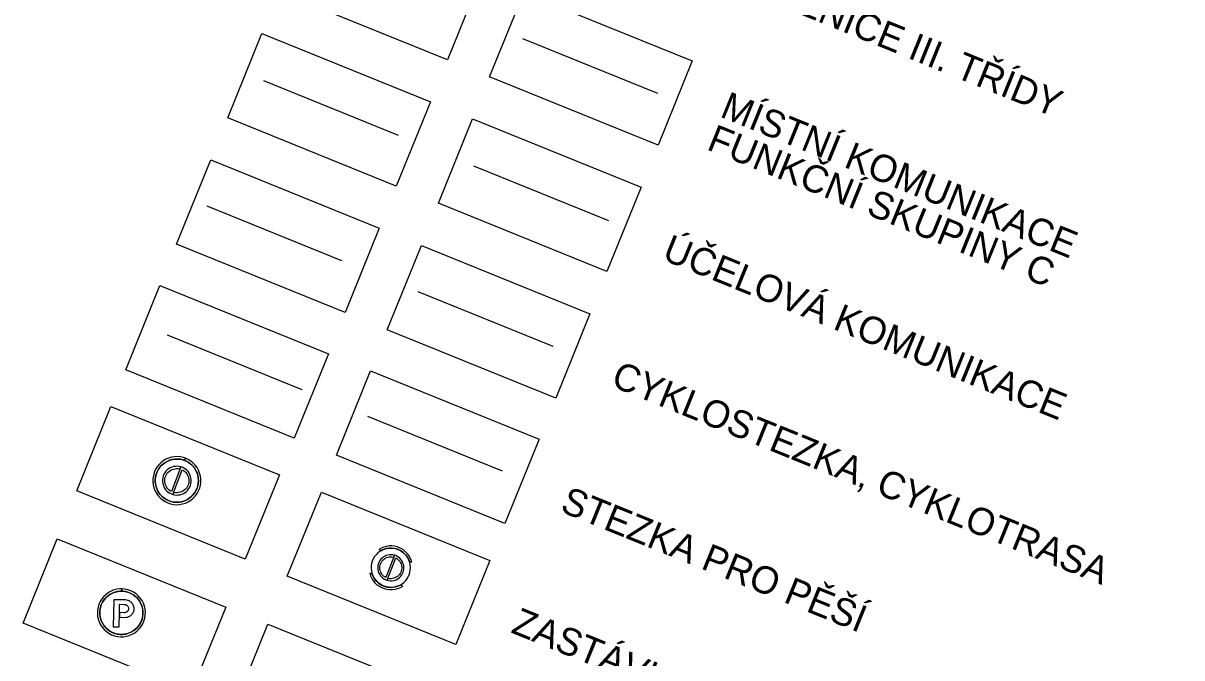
# Model space of a CAD drawing. Extents: x -522763 to -519637, y -1191176 to -1188936.
# Drawn here: x -522606 to -521969, y -1189589 to -1189240 of the extents above; entities that cross this region are included whole.
import ezdxf

# ---------------------------------------------------------------- set-up
doc = ezdxf.new("R2010")
doc.units = 0
for name, color, linetype in [('cyklostezka_s', 7, 'Continuous'), ('Implicitní', 7, 'Continuous'), ('ložisk_nerost', 7, 'Continuous'), ('MK_C_n', 7, 'Continuous'), ('stezka_s', 7, 'Continuous'), ('zast_HD_n', 7, 'Continuous'), ('zast_HD_s', 7, 'Continuous')]:
    doc.layers.add(name, color=color, linetype=linetype)

msp = doc.modelspace()

# ---------------------------------------------------------------- linework, layer by layer
at = {"layer": 'cyklostezka_s'}
msp.add_line((-522505.25, -1189340.46), (-522431.11, -1189370.51), dxfattribs=at)
at = {"layer": 'Implicitní'}
for p, q in [((-522474.07, -1189271.68), (-522399.92, -1189301.73)), ((-522358.48, -1189318.53), (-522284.34, -1189348.58)), ((-522389.06, -1189387.55), (-522314.92, -1189417.6)), ((-522416.84, -1189456.08), (-522342.7, -1189486.13))]:
    msp.add_line(p, q, dxfattribs=at)
for points in [[(-522446.72, -1189176.27), (-522354.04, -1189213.83), (-522372.82, -1189260.17), (-522465.5, -1189222.61)], [(-522330.87, -1189223.22), (-522238.19, -1189260.78), (-522256.97, -1189307.12), (-522349.65, -1189269.56)], [(-522474.89, -1189245.78), (-522382.21, -1189283.34), (-522400.99, -1189329.68), (-522493.67, -1189292.12)], [(-522359.04, -1189292.73), (-522266.36, -1189330.29), (-522285.14, -1189376.63), (-522377.82, -1189339.07)], [(-522503.06, -1189315.29), (-522410.38, -1189352.85), (-522429.16, -1189399.19), (-522521.84, -1189361.63)], [(-522387.21, -1189362.24), (-522294.53, -1189399.8), (-522313.31, -1189446.14), (-522405.99, -1189408.58)], [(-522531, -1189384.24), (-522438.33, -1189421.8), (-522457.11, -1189468.14), (-522549.78, -1189430.58)], [(-522415.16, -1189431.19), (-522322.48, -1189468.75), (-522341.26, -1189515.09), (-522433.94, -1189477.53)], [(-522558, -1189450.84), (-522465.32, -1189488.4), (-522484.1, -1189534.74), (-522576.78, -1189497.18)], [(-522442.15, -1189497.79), (-522349.47, -1189535.35), (-522368.25, -1189581.69), (-522460.93, -1189544.13)], [(-522587.44, -1189523.5), (-522494.77, -1189561.06), (-522513.55, -1189607.4), (-522606.22, -1189569.84)], [(-522471.6, -1189570.45), (-522378.92, -1189608.01), (-522397.7, -1189654.35), (-522490.38, -1189616.79)]]:
    msp.add_lwpolyline(points, close=True, dxfattribs=at)
at = {"layer": 'ložisk_nerost'}
for points in [[(-522551.92, -1189550.99), (-522553.02, -1189551.02), (-522554.68, -1189551.23), (-522556.29, -1189551.64), (-522557.85, -1189552.26), (-522559.31, -1189553.07), (-522560.66, -1189554.05), (-522561.87, -1189555.2), (-522562.93, -1189556.49), (-522563.81, -1189557.91), (-522564.52, -1189559.42), (-522565.02, -1189561.01), (-522565.32, -1189562.66), (-522565.41, -1189564.32), (-522565.29, -1189565.99), (-522564.96, -1189567.63), (-522564.42, -1189569.21), (-522563.69, -1189570.71), (-522562.78, -1189572.11), (-522561.7, -1189573.38), (-522560.46, -1189574.51), (-522559.1, -1189575.47), (-522557.62, -1189576.25), (-522556.06, -1189576.83), (-522554.43, -1189577.22), (-522552.77, -1189577.4), (-522551.1, -1189577.36), (-522549.45, -1189577.12), (-522547.84, -1189576.67), (-522546.3, -1189576.02), (-522544.86, -1189575.18), (-522543.53, -1189574.17), (-522542.35, -1189572.99), (-522541.31, -1189571.68), (-522540.46, -1189570.25), (-522539.79, -1189568.72), (-522539.32, -1189567.11), (-522539.05, -1189565.47), (-522539, -1189563.8), (-522539.15, -1189562.13), (-522539.52, -1189560.5), (-522540.09, -1189558.93), (-522540.85, -1189557.45), (-522541.79, -1189556.07), (-522542.9, -1189554.82), (-522544.16, -1189553.72), (-522545.55, -1189552.79), (-522547.04, -1189552.04), (-522548.61, -1189551.49), (-522550.25, -1189551.14), (-522551.91, -1189551)], [(-522540.32, -1189564.46), (-522540.38, -1189562.96), (-522540.63, -1189561.47), (-522541.07, -1189560.04), (-522541.68, -1189558.66), (-522542.46, -1189557.38), (-522543.4, -1189556.21), (-522544.48, -1189555.16), (-522545.68, -1189554.26), (-522546.99, -1189553.52), (-522548.38, -1189552.94), (-522549.83, -1189552.55), (-522551.32, -1189552.34), (-522552.82, -1189552.33), (-522554.31, -1189552.5), (-522555.77, -1189552.86), (-522557.18, -1189553.4), (-522558.5, -1189554.12), (-522559.72, -1189554.99), (-522560.82, -1189556.01), (-522561.79, -1189557.17), (-522562.6, -1189558.43), (-522563.24, -1189559.79), (-522563.71, -1189561.22), (-522563.99, -1189562.7), (-522564.09, -1189564.2), (-522564, -1189565.7), (-522563.71, -1189567.17), (-522563.25, -1189568.6), (-522562.6, -1189569.96), (-522561.79, -1189571.22), (-522560.83, -1189572.38), (-522559.73, -1189573.4), (-522558.51, -1189574.28), (-522557.19, -1189574.99), (-522555.78, -1189575.54), (-522554.33, -1189575.9), (-522552.83, -1189576.07), (-522551.33, -1189576.06), (-522549.84, -1189575.85), (-522548.39, -1189575.46), (-522547, -1189574.89), (-522545.69, -1189574.15), (-522544.49, -1189573.25), (-522543.41, -1189572.2), (-522542.47, -1189571.03), (-522541.69, -1189569.75), (-522541.07, -1189568.38), (-522540.63, -1189566.94), (-522540.38, -1189565.46), (-522540.32, -1189564.46)], [(-522551.94, -1189552.31), (-522550.95, -1189552.38), (-522549.47, -1189552.63), (-522548.03, -1189553.07), (-522546.66, -1189553.68), (-522545.38, -1189554.46), (-522544.2, -1189555.4), (-522543.16, -1189556.48), (-522542.26, -1189557.69), (-522541.51, -1189558.99), (-522540.94, -1189560.38), (-522540.55, -1189561.83), (-522540.34, -1189563.32), (-522540.33, -1189564.83), (-522540.5, -1189566.32), (-522540.86, -1189567.78), (-522541.41, -1189569.18), (-522542.12, -1189570.5), (-522543, -1189571.72), (-522544.02, -1189572.83), (-522545.17, -1189573.79), (-522546.44, -1189574.6), (-522547.8, -1189575.24), (-522549.22, -1189575.71), (-522550.7, -1189575.99), (-522552.2, -1189576.09), (-522553.7, -1189575.99), (-522555.18, -1189575.71), (-522556.61, -1189575.24), (-522557.96, -1189574.6), (-522559.23, -1189573.79), (-522560.38, -1189572.83), (-522561.41, -1189571.72), (-522562.28, -1189570.5), (-522563, -1189569.18), (-522563.54, -1189567.78), (-522563.9, -1189566.32), (-522564.07, -1189564.83), (-522564.06, -1189563.32), (-522563.85, -1189561.83), (-522563.46, -1189560.38), (-522562.89, -1189558.99), (-522562.15, -1189557.69), (-522561.25, -1189556.48), (-522560.2, -1189555.4), (-522559.03, -1189554.47), (-522557.74, -1189553.68), (-522556.37, -1189553.07), (-522554.93, -1189552.63), (-522553.45, -1189552.38), (-522551.95, -1189552.31)], [(-522551.95, -1189552.31), (-522551.92, -1189550.99)], [(-522551.91, -1189551), (-522551.94, -1189552.31)], [(-522549.88, -1189557.12), (-522556.33, -1189556.98), (-522556.65, -1189571.87), (-522553.48, -1189571.94), (-522553.31, -1189564.09)], [(-522550.09, -1189566.74), (-522549.38, -1189566.63), (-522548.91, -1189566.53), (-522548.56, -1189566.42), (-522548.2, -1189566.31), (-522547.96, -1189566.2), (-522547.73, -1189566.08), (-522547.37, -1189565.86), (-522547.01, -1189565.63), (-522546.77, -1189565.4), (-522546.53, -1189565.17), (-522546.29, -1189564.94), (-522546.05, -1189564.6), (-522545.81, -1189564.25), (-522545.69, -1189564.02), (-522545.57, -1189563.79), (-522545.44, -1189563.44), (-522545.32, -1189563.09), (-522545.19, -1189562.5), (-522545.18, -1189562.15), (-522545.17, -1189561.68), (-522545.27, -1189561.1), (-522545.27, -1189560.98), (-522545.38, -1189560.62), (-522545.49, -1189560.27), (-522545.72, -1189559.79), (-522545.94, -1189559.44), (-522546.17, -1189559.08), (-522546.4, -1189558.84), (-522546.63, -1189558.6), (-522546.86, -1189558.36), (-522547.2, -1189558.12), (-522547.55, -1189557.88), (-522547.78, -1189557.76), (-522548.01, -1189557.63), (-522548.36, -1189557.51), (-522548.59, -1189557.39), (-522549.18, -1189557.26), (-522549.88, -1189557.12)], [(-522553.26, -1189564.09), (-522553.32, -1189566.67)], [(-522553.31, -1189564.09), (-522553.21, -1189559.51)], [(-522550.73, -1189564.14), (-522553.26, -1189564.09)], [(-522553.21, -1189559.51), (-522550.64, -1189559.57)], [(-522550.64, -1189559.57), (-522550.52, -1189559.57), (-522550.4, -1189559.58), (-522549.82, -1189559.71), (-522549.59, -1189559.83), (-522549.35, -1189559.95), (-522549.12, -1189560.07), (-522548.89, -1189560.31), (-522548.66, -1189560.55), (-522548.44, -1189560.91), (-522548.33, -1189561.26), (-522548.22, -1189561.85), (-522548.23, -1189562.08), (-522548.35, -1189562.55), (-522548.48, -1189562.9), (-522548.72, -1189563.25), (-522548.84, -1189563.36), (-522549.08, -1189563.59), (-522549.44, -1189563.82), (-522549.67, -1189563.93), (-522550.03, -1189564.04), (-522550.5, -1189564.15), (-522550.73, -1189564.14)], [(-522553.32, -1189566.67), (-522550.09, -1189566.74)]]:
    msp.add_lwpolyline(points, dxfattribs=at)
at = {"layer": 'MK_C_n'}
msp.add_line((-522331.55, -1189248.52), (-522257.41, -1189278.57), dxfattribs=at)
at = {"layer": 'stezka_s'}
msp.add_line((-522527.05, -1189411.42), (-522452.9, -1189441.47), dxfattribs=at)
at = {"layer": 'zast_HD_n'}
msp.add_line((-522406.01, -1189546.33), (-522406.01, -1189546.33), dxfattribs=at)
for points in [[(-522393.93, -1189543.3), (-522393.52, -1189542), (-522393.28, -1189540.65), (-522393.21, -1189539.29), (-522393.31, -1189537.93), (-522393.59, -1189536.59), (-522394.03, -1189535.3), (-522394.63, -1189534.07), (-522395.38, -1189532.93), (-522396.27, -1189531.89), (-522397.28, -1189530.97), (-522398.4, -1189530.19), (-522399.61, -1189529.56), (-522400.89, -1189529.08), (-522402.22, -1189528.77), (-522403.58, -1189528.63), (-522404.95, -1189528.66), (-522406.3, -1189528.86), (-522407.61, -1189529.23), (-522408.87, -1189529.77), (-522410.05, -1189530.46), (-522411.13, -1189531.29), (-522412.1, -1189532.26), (-522412.94, -1189533.33), (-522413.64, -1189534.51), (-522414.18, -1189535.76), (-522414.57, -1189537.08), (-522414.78, -1189538.43), (-522414.82, -1189539.79), (-522414.69, -1189541.15), (-522414.38, -1189542.48), (-522413.91, -1189543.77), (-522413.29, -1189544.98), (-522412.51, -1189546.11), (-522411.6, -1189547.12), (-522410.57, -1189548.02), (-522409.43, -1189548.78), (-522408.21, -1189549.39), (-522406.92, -1189549.84), (-522405.58, -1189550.12), (-522404.22, -1189550.23), (-522402.85, -1189550.17), (-522401.51, -1189549.94), (-522400.2, -1189549.54), (-522398.96, -1189548.98), (-522397.79, -1189548.26), (-522396.73, -1189547.41), (-522395.78, -1189546.42), (-522394.96, -1189545.33), (-522394.29, -1189544.14), (-522393.93, -1189543.3)], [(-522402.04, -1189532.52), (-522402.92, -1189532.32), (-522403.83, -1189532.24), (-522404.74, -1189532.27), (-522405.63, -1189532.42), (-522406.51, -1189532.68), (-522407.34, -1189533.04), (-522408.12, -1189533.51), (-522408.83, -1189534.08), (-522409.47, -1189534.72), (-522410.01, -1189535.45), (-522410.47, -1189536.24), (-522410.82, -1189537.07), (-522411.06, -1189537.95), (-522411.19, -1189538.85), (-522411.2, -1189539.76), (-522411.11, -1189540.66), (-522410.89, -1189541.54), (-522410.57, -1189542.4), (-522410.14, -1189543.2), (-522409.62, -1189543.94), (-522409, -1189544.61), (-522408.31, -1189545.19), (-522407.55, -1189545.69), (-522406.73, -1189546.08), (-522406.06, -1189546.32)], [(-522399.72, -1189528.21), (-522400.43, -1189527.97), (-522401.9, -1189527.6), (-522403.41, -1189527.43), (-522404.93, -1189527.45), (-522406.43, -1189527.66), (-522407.9, -1189528.06), (-522409.3, -1189528.64), (-522410.62, -1189529.39)], [(-522410.62, -1189529.39), (-522409.2, -1189529.93)], [(-522406.72, -1189544.83), (-522407.38, -1189544.44), (-522407.98, -1189543.98), (-522408.53, -1189543.44), (-522409, -1189542.84), (-522409.39, -1189542.19), (-522409.7, -1189541.49), (-522409.91, -1189540.76), (-522410.03, -1189540), (-522410.06, -1189539.24), (-522409.99, -1189538.48), (-522409.82, -1189537.74), (-522409.56, -1189537.02), (-522409.21, -1189536.34), (-522408.78, -1189535.71), (-522408.28, -1189535.14), (-522407.7, -1189534.63), (-522407.07, -1189534.21), (-522406.39, -1189533.87), (-522405.67, -1189533.61), (-522404.92, -1189533.45), (-522404.16, -1189533.39), (-522403.4, -1189533.42), (-522402.64, -1189533.55), (-522402.45, -1189533.59)], [(-522409.2, -1189529.93), (-522408.16, -1189529.44), (-522406.87, -1189528.99), (-522405.53, -1189528.72), (-522404.17, -1189528.62), (-522402.8, -1189528.68), (-522401.46, -1189528.92), (-522400.15, -1189529.33)], [(-522401.99, -1189532.53), (-522406.72, -1189544.83)], [(-522406.01, -1189546.33), (-522405.12, -1189546.52), (-522404.22, -1189546.61), (-522403.31, -1189546.57), (-522402.42, -1189546.43), (-522401.54, -1189546.17), (-522400.71, -1189545.8), (-522399.94, -1189545.33), (-522399.22, -1189544.77), (-522398.59, -1189544.12), (-522398.04, -1189543.39), (-522397.58, -1189542.61), (-522397.23, -1189541.77), (-522396.99, -1189540.89), (-522396.86, -1189539.99), (-522396.85, -1189539.09), (-522396.94, -1189538.18), (-522397.16, -1189537.3), (-522397.48, -1189536.45), (-522397.91, -1189535.65), (-522398.43, -1189534.91), (-522399.05, -1189534.24), (-522399.74, -1189533.65), (-522400.5, -1189533.16), (-522401.32, -1189532.76), (-522401.99, -1189532.53)], [(-522402.45, -1189533.59), (-522402.04, -1189532.51)], [(-522400.14, -1189529.34), (-522399.09, -1189529.81), (-522397.92, -1189530.51), (-522396.84, -1189531.35), (-522395.88, -1189532.32), (-522395.05, -1189533.4), (-522394.36, -1189534.58), (-522393.83, -1189535.84)], [(-522392.41, -1189536.39), (-522392.62, -1189535.67), (-522393.18, -1189534.26), (-522393.92, -1189532.93), (-522394.82, -1189531.71), (-522395.87, -1189530.61), (-522397.04, -1189529.65), (-522398.33, -1189528.85), (-522399.71, -1189528.22)], [(-522406.06, -1189546.32), (-522401.33, -1189534.02)], [(-522401.33, -1189534.02), (-522400.67, -1189534.4), (-522400.06, -1189534.86), (-522399.52, -1189535.4), (-522399.05, -1189536), (-522398.66, -1189536.66), (-522398.35, -1189537.36), (-522398.14, -1189538.09), (-522398.01, -1189538.84), (-522397.99, -1189539.6), (-522398.06, -1189540.37), (-522398.23, -1189541.11), (-522398.49, -1189541.83), (-522398.84, -1189542.51), (-522399.27, -1189543.14), (-522399.77, -1189543.71), (-522400.35, -1189544.21), (-522400.98, -1189544.64), (-522401.66, -1189544.98), (-522402.38, -1189545.23), (-522403.13, -1189545.39), (-522403.89, -1189545.46), (-522404.65, -1189545.43), (-522405.4, -1189545.3), (-522405.6, -1189545.25)], [(-522393.83, -1189535.84), (-522392.41, -1189536.39)], [(-522415.64, -1189542.46), (-522415.17, -1189543.89), (-522414.52, -1189545.26), (-522413.7, -1189546.54), (-522412.72, -1189547.7), (-522411.61, -1189548.73), (-522410.37, -1189549.61), (-522409.04, -1189550.33), (-522407.62, -1189550.88), (-522406.15, -1189551.24), (-522404.64, -1189551.41), (-522403.12, -1189551.4), (-522401.62, -1189551.19), (-522400.15, -1189550.79), (-522398.75, -1189550.21), (-522397.43, -1189549.46)], [(-522414.22, -1189543), (-522415.64, -1189542.46)], [(-522398.85, -1189548.91), (-522399.7, -1189549.33), (-522400.99, -1189549.79), (-522402.32, -1189550.09), (-522403.68, -1189550.22), (-522405.05, -1189550.18), (-522406.4, -1189549.97), (-522407.71, -1189549.58), (-522408.96, -1189549.04), (-522410.13, -1189548.34), (-522411.21, -1189547.5), (-522412.17, -1189546.53), (-522413, -1189545.44), (-522413.69, -1189544.26), (-522414.22, -1189543)], [(-522405.6, -1189545.25), (-522406.01, -1189546.33)], [(-522397.43, -1189549.46), (-522398.85, -1189548.91)]]:
    msp.add_lwpolyline(points, dxfattribs=at)
at = {"layer": 'zast_HD_s'}
msp.add_line((-522523.89, -1189499.16), (-522523.89, -1189499.15), dxfattribs=at)
for points in [[(-522516.99, -1189479.22), (-522518.03, -1189478.87), (-522519.66, -1189478.51), (-522521.32, -1189478.35), (-522522.99, -1189478.41), (-522524.64, -1189478.67), (-522526.24, -1189479.15), (-522527.77, -1189479.82), (-522529.2, -1189480.68), (-522530.52, -1189481.71), (-522531.69, -1189482.9), (-522532.7, -1189484.23), (-522533.54, -1189485.67), (-522534.18, -1189487.21), (-522534.63, -1189488.82), (-522534.87, -1189490.47), (-522534.9, -1189492.14), (-522534.72, -1189493.8), (-522534.34, -1189495.43), (-522533.75, -1189496.99), (-522532.96, -1189498.47), (-522532, -1189499.83), (-522530.88, -1189501.06), (-522529.6, -1189502.14), (-522528.2, -1189503.06), (-522526.7, -1189503.78), (-522525.12, -1189504.32), (-522523.48, -1189504.64), (-522521.81, -1189504.76), (-522520.15, -1189504.67), (-522518.5, -1189504.37), (-522516.91, -1189503.86), (-522515.4, -1189503.16), (-522513.98, -1189502.27), (-522512.69, -1189501.21), (-522511.55, -1189499.99), (-522510.56, -1189498.65), (-522509.76, -1189497.18), (-522509.14, -1189495.63), (-522508.73, -1189494.01), (-522508.52, -1189492.35), (-522508.53, -1189490.68), (-522508.74, -1189489.03), (-522509.17, -1189487.41), (-522509.79, -1189485.86), (-522510.6, -1189484.4), (-522511.59, -1189483.06), (-522512.75, -1189481.85), (-522514.04, -1189480.8), (-522515.46, -1189479.92), (-522516.98, -1189479.22)], [(-522510.61, -1189495.81), (-522510.16, -1189494.37), (-522509.89, -1189492.89), (-522509.82, -1189491.39), (-522509.94, -1189489.89), (-522510.24, -1189488.42), (-522510.73, -1189487), (-522511.39, -1189485.65), (-522512.22, -1189484.39), (-522513.2, -1189483.26), (-522514.31, -1189482.25), (-522515.54, -1189481.39), (-522516.88, -1189480.69), (-522518.29, -1189480.17), (-522519.75, -1189479.83), (-522521.24, -1189479.67), (-522522.75, -1189479.71), (-522524.23, -1189479.94), (-522525.68, -1189480.35), (-522527.06, -1189480.94), (-522528.36, -1189481.7), (-522529.55, -1189482.62), (-522530.61, -1189483.68), (-522531.54, -1189484.86), (-522532.3, -1189486.16), (-522532.9, -1189487.54), (-522533.32, -1189488.98), (-522533.55, -1189490.47), (-522533.59, -1189491.97), (-522533.44, -1189493.46), (-522533.11, -1189494.93), (-522532.59, -1189496.34), (-522531.9, -1189497.68), (-522531.05, -1189498.91), (-522530.04, -1189500.03), (-522528.91, -1189501.02), (-522527.66, -1189501.85), (-522526.31, -1189502.52), (-522524.89, -1189503.01), (-522523.42, -1189503.32), (-522521.92, -1189503.44), (-522520.42, -1189503.37), (-522518.94, -1189503.12), (-522517.5, -1189502.67), (-522516.13, -1189502.05), (-522514.85, -1189501.27), (-522513.68, -1189500.32), (-522512.64, -1189499.24), (-522511.74, -1189498.03), (-522511, -1189496.73), (-522510.61, -1189495.81)], [(-522517.45, -1189480.45), (-522516.54, -1189480.85), (-522515.23, -1189481.58), (-522514.03, -1189482.48), (-522512.94, -1189483.52), (-522512, -1189484.69), (-522511.21, -1189485.97), (-522510.59, -1189487.34), (-522510.15, -1189488.78), (-522509.89, -1189490.26), (-522509.82, -1189491.76), (-522509.94, -1189493.26), (-522510.25, -1189494.73), (-522510.74, -1189496.15), (-522511.41, -1189497.5), (-522512.24, -1189498.75), (-522513.23, -1189499.88), (-522514.35, -1189500.89), (-522515.58, -1189501.74), (-522516.92, -1189502.43), (-522518.33, -1189502.95), (-522519.79, -1189503.29), (-522521.29, -1189503.44), (-522522.79, -1189503.39), (-522524.28, -1189503.16), (-522525.72, -1189502.75), (-522527.1, -1189502.15), (-522528.39, -1189501.39), (-522529.58, -1189500.46), (-522530.64, -1189499.4), (-522531.56, -1189498.21), (-522532.32, -1189496.91), (-522532.91, -1189495.53), (-522533.32, -1189494.08), (-522533.55, -1189492.6), (-522533.59, -1189491.1), (-522533.44, -1189489.6), (-522533.1, -1189488.14), (-522532.57, -1189486.73), (-522531.88, -1189485.4), (-522531.02, -1189484.16), (-522530.01, -1189483.05), (-522528.87, -1189482.07), (-522527.62, -1189481.24), (-522526.27, -1189480.58), (-522524.85, -1189480.09), (-522523.37, -1189479.78), (-522521.88, -1189479.67), (-522520.37, -1189479.74), (-522518.9, -1189480), (-522517.46, -1189480.45)], [(-522517.46, -1189480.45), (-522516.99, -1189479.22)], [(-522516.98, -1189479.22), (-522517.45, -1189480.45)], [(-522519.53, -1189483.95), (-522520.51, -1189483.74), (-522521.5, -1189483.65), (-522522.5, -1189483.69), (-522523.49, -1189483.85), (-522524.44, -1189484.14), (-522525.36, -1189484.54), (-522526.21, -1189485.06), (-522527, -1189485.68), (-522527.7, -1189486.39), (-522528.3, -1189487.19), (-522528.8, -1189488.06), (-522529.18, -1189488.98), (-522529.45, -1189489.94), (-522529.59, -1189490.93), (-522529.6, -1189491.93), (-522529.49, -1189492.93), (-522529.26, -1189493.9), (-522528.9, -1189494.83), (-522528.43, -1189495.71), (-522527.85, -1189496.53), (-522527.18, -1189497.26), (-522526.41, -1189497.91), (-522525.57, -1189498.45), (-522524.67, -1189498.88), (-522523.94, -1189499.14)], [(-522524.66, -1189497.5), (-522525.39, -1189497.08), (-522526.06, -1189496.57), (-522526.66, -1189495.98), (-522527.18, -1189495.32), (-522527.61, -1189494.6), (-522527.94, -1189493.83), (-522528.18, -1189493.03), (-522528.32, -1189492.2), (-522528.35, -1189491.36), (-522528.27, -1189490.52), (-522528.09, -1189489.71), (-522527.8, -1189488.92), (-522527.42, -1189488.17), (-522526.95, -1189487.47), (-522526.39, -1189486.84), (-522525.76, -1189486.29), (-522525.06, -1189485.82), (-522524.31, -1189485.45), (-522523.52, -1189485.17), (-522522.7, -1189484.99), (-522521.86, -1189484.91), (-522521.03, -1189484.95), (-522520.2, -1189485.09), (-522519.98, -1189485.14)], [(-522519.48, -1189483.97), (-522524.66, -1189497.5)], [(-522523.94, -1189499.14), (-522518.75, -1189485.61)], [(-522523.89, -1189499.15), (-522522.91, -1189499.37), (-522521.91, -1189499.46), (-522520.91, -1189499.42), (-522519.93, -1189499.26), (-522518.97, -1189498.97), (-522518.06, -1189498.57), (-522517.2, -1189498.05), (-522516.42, -1189497.43), (-522515.72, -1189496.72), (-522515.12, -1189495.92), (-522514.62, -1189495.05), (-522514.23, -1189494.13), (-522513.97, -1189493.17), (-522513.83, -1189492.18), (-522513.81, -1189491.18), (-522513.92, -1189490.18), (-522514.16, -1189489.21), (-522514.51, -1189488.28), (-522514.98, -1189487.4), (-522515.56, -1189486.58), (-522516.24, -1189485.85), (-522517, -1189485.2), (-522517.84, -1189484.66), (-522518.74, -1189484.22), (-522519.48, -1189483.97)], [(-522518.75, -1189485.61), (-522518.03, -1189486.03), (-522517.36, -1189486.54), (-522516.76, -1189487.13), (-522516.24, -1189487.78), (-522515.81, -1189488.51), (-522515.47, -1189489.27), (-522515.23, -1189490.08), (-522515.1, -1189490.91), (-522515.07, -1189491.75), (-522515.15, -1189492.59), (-522515.33, -1189493.4), (-522515.61, -1189494.19), (-522516, -1189494.94), (-522516.47, -1189495.64), (-522517.02, -1189496.26), (-522517.66, -1189496.82), (-522518.35, -1189497.29), (-522519.1, -1189497.66), (-522519.89, -1189497.94), (-522520.71, -1189498.12), (-522521.55, -1189498.19), (-522522.39, -1189498.16), (-522523.22, -1189498.02), (-522523.43, -1189497.97)], [(-522519.98, -1189485.14), (-522519.53, -1189483.95)], [(-522523.43, -1189497.97), (-522523.89, -1189499.16)]]:
    msp.add_lwpolyline(points, dxfattribs=at)

# ---------------------------------------------------------------- texts
at = {"layer": 'Implicitní'}
for s, p in [('SILNICE III. TŘÍDY', (-522197.77, -1189227.61)), ('MÍSTNÍ KOMUNIKACE ', (-522223.58, -1189291.3)), ('FUNKČNÍ SKUPINY C', (-522230.87, -1189309.29)), ('ÚČELOVÁ KOMUNIKACE', (-522255.4, -1189369.8)), ('CYKLOSTEZKA, CYKLOTRASA ', (-522283.57, -1189439.31)), ('STEZKA PRO PĚŠÍ', (-522311.52, -1189508.27)), ('ZASTÁVKA HROMADNÉ DOPRAVY OSOB', (-522338.51, -1189574.86))]:
    msp.add_text(s, height=15, rotation=337.93793, dxfattribs=at).set_placement(p)

doc.saveas('drawing.dxf')
